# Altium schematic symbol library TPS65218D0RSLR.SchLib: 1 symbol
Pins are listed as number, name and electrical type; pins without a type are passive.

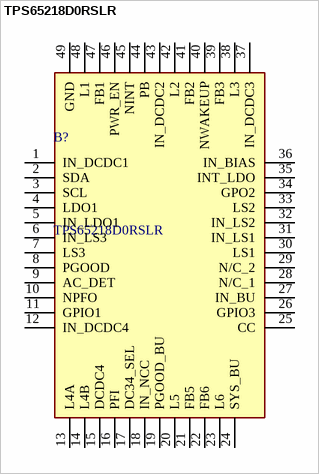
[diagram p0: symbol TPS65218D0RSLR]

## TPS65218D0RSLR
designator B?
Power Management Specialised - PMIC; Manufacturer_Name: Texas Instruments; Geometry.Height: 1mm
footprint QFN40P600X600X100-49N-D
pins: 1 IN_DCDC1, 2 SDA, 3 SCL, 4 LDO1, 5 IN_LDO1, 6 IN_LS3, 7 LS3, 8 PGOOD, 9 AC_DET, 10 NPFO, 11 GPIO1, 12 IN_DCDC4, 13 L4A, 14 L4B, 15 DCDC4, 16 PFI, 17 DC34_SEL, 18 IN_NCC, 19 PGOOD_BU, 20 L5, 21 FB5, 22 FB6, 23 L6, 24 SYS_BU, 25 CC, 26 GPIO3, 27 IN_BU, 28 N/C_1, 29 N/C_2, 30 LS1, 31 IN_LS1, 32 IN_LS2, 33 LS2, 34 GPO2, 35 INT_LDO, 36 IN_BIAS, 37 IN_DCDC3, 38 L3, 39 FB3, 40 NWAKEUP, 41 FB2, 42 L2, 43 IN_DCDC2, 44 PB, 45 NINT, 46 PWR_EN, 47 FB1, 48 L1, 49 GND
